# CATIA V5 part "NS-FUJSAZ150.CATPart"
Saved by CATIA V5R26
Part number: NS-FUJSAZ150
Bounding box of the stored display mesh (mm): x -60 to 120, y 0 to 198, z -60 to 60
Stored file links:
  R:\Document\坂尻\その他\ナベヤデータ変換\安全カバーキャスター\MCBJSAZ150\NS-FUJSAZ150.CATPart
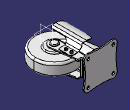
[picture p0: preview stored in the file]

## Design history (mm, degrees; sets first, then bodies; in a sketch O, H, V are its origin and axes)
Body1 (main body)
  Solid1: solid without history
  Body2
    Solid2: solid without history
  Assemble1: tool Body2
